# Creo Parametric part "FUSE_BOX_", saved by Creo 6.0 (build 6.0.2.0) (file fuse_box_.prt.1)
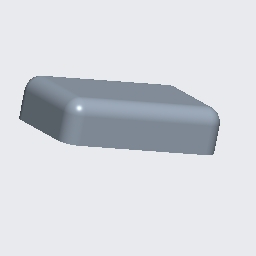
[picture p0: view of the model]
Units: Inch lbm Second (Pro/E Default); INCH, POUND, SECS

Created from: INLBS_PART_SOLID.PRT

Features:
  1. datum plane "RIGHT"
  2. datum plane "TOP"
  3. datum plane "FRONT"
  4. coordinate system
  5. sketch "Sketch 1"
  6. extrusion "Extrude 1"
  7. round "Round 1"

Surfaces: 8 cylinder, 6 plane, 4 torus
